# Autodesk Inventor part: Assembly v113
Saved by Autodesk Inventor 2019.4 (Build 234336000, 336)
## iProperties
Created: 2020-02
Part Number: Assembly v113
Material: Generic
Document SubType Name: Modeling
Designer: Administrator
Density: 1 g/cm^3
Appearance: Default
Author: Administrator
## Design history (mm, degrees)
feature "Body3"
body "Solid1"
